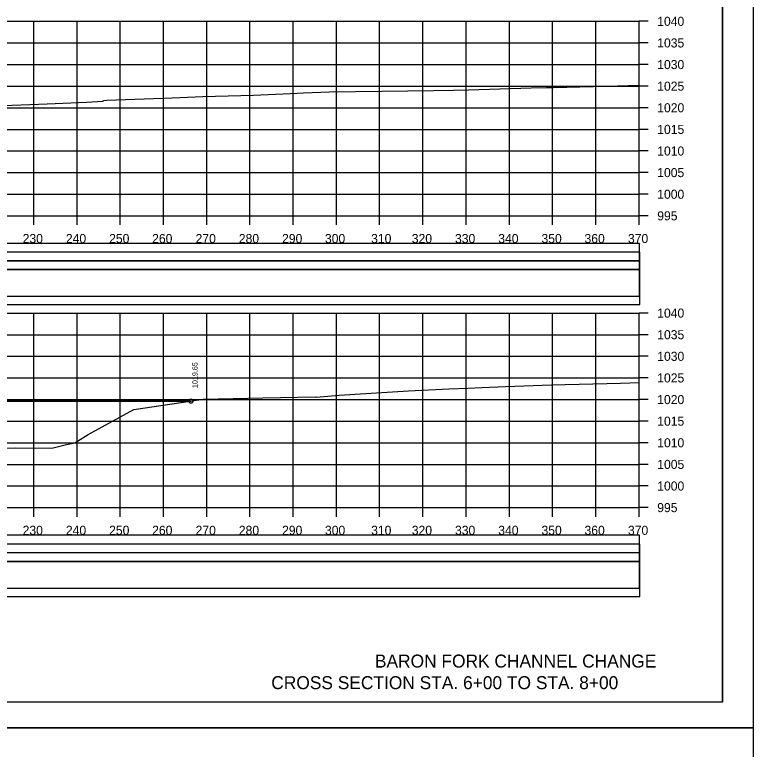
# Model space of a CAD drawing. Extents: x 1370565 to 1374448, y 301010 to 304637.
# Drawn here: x 1374277.1 to 1374447.9, y 301728.1 to 301898 of the extents above; entities that cross this region are included whole.
import ezdxf

# ---------------------------------------------------------------- set-up
doc = ezdxf.new("R2010")
doc.units = 0
for name, color, linetype in [('Default', 7, 'Continuous'), ('R_Axis', 7, 'Continuous'), ('R_Axis Annot', 7, 'Continuous'), ('R_Border', 7, 'Continuous'), ('R_Contours', 7, 'Continuous'), ('R_Draft', 7, 'Continuous'), ('R_Drive', 7, 'Continuous'), ('R_Exist Surface', 7, 'Continuous'), ('R_Fin Surface', 7, 'Continuous'), ('R_Grid', 7, 'Continuous'), ('R_No Plot', 7, 'Continuous'), ('R_Xsect Elev', 7, 'Continuous')]:
    doc.layers.add(name, color=color, linetype=linetype)

msp = doc.modelspace()

# ---------------------------------------------------------------- linework, layer by layer
at = {"layer": 'Default'}
for points in [[(1373981.44, 301841.09), (1374421.61, 301841.09), (1374421.61, 301845.08), (1373981.44, 301845.08)], [(1373981.44, 301832.86), (1374421.61, 301832.86), (1374421.61, 301841.01), (1373981.44, 301841.01)], [(1373981.44, 301773.59), (1374421.61, 301773.59), (1374421.61, 301777.58), (1373981.44, 301777.58)], [(1373981.44, 301765.36), (1374421.61, 301765.36), (1374421.61, 301773.51), (1373981.44, 301773.51)]]:
    msp.add_lwpolyline(points, close=True, dxfattribs=at)
at = {"layer": 'R_Axis'}
for p, q in [((1374421.52, 301851.46), (1374421.52, 301896.46)), ((1374423.62, 301896.46), (1374421.52, 301896.46)), ((1374423.62, 301891.46), (1374421.52, 301891.46)), ((1374423.62, 301886.46), (1374421.52, 301886.46)), ((1374423.62, 301881.46), (1374421.52, 301881.46)), ((1374423.62, 301876.46), (1374421.52, 301876.46)), ((1374423.62, 301871.46), (1374421.52, 301871.46)), ((1374423.62, 301866.46), (1374421.52, 301866.46)), ((1374423.62, 301861.46), (1374421.52, 301861.46)), ((1374423.62, 301856.46), (1374421.52, 301856.46)), ((1373981.52, 301851.46), (1374421.52, 301851.46)), ((1374281.52, 301849.36), (1374281.52, 301851.46)), ((1374291.52, 301849.36), (1374291.52, 301851.46)), ((1374301.52, 301849.36), (1374301.52, 301851.46)), ((1374311.52, 301849.36), (1374311.52, 301851.46)), ((1374321.52, 301849.36), (1374321.52, 301851.46)), ((1374331.52, 301849.36), (1374331.52, 301851.46)), ((1374341.52, 301849.36), (1374341.52, 301851.46)), ((1374351.52, 301849.36), (1374351.52, 301851.46)), ((1374361.52, 301849.36), (1374361.52, 301851.46)), ((1374371.52, 301849.36), (1374371.52, 301851.46)), ((1374381.52, 301849.36), (1374381.52, 301851.46)), ((1374391.52, 301849.36), (1374391.52, 301851.46)), ((1374401.52, 301849.36), (1374401.52, 301851.46)), ((1374411.52, 301849.36), (1374411.52, 301851.46)), ((1374421.52, 301849.36), (1374421.52, 301851.46)), ((1374423.62, 301851.46), (1374421.52, 301851.46)), ((1374421.52, 301783.96), (1374421.52, 301828.96)), ((1374423.62, 301828.96), (1374421.52, 301828.96)), ((1374423.62, 301823.96), (1374421.52, 301823.96)), ((1374423.62, 301818.96), (1374421.52, 301818.96)), ((1374423.62, 301813.96), (1374421.52, 301813.96)), ((1374423.62, 301808.96), (1374421.52, 301808.96)), ((1374423.62, 301803.96), (1374421.52, 301803.96)), ((1374423.62, 301798.96), (1374421.52, 301798.96)), ((1374423.62, 301793.96), (1374421.52, 301793.96)), ((1374423.62, 301788.96), (1374421.52, 301788.96)), ((1373981.52, 301783.96), (1374421.52, 301783.96)), ((1374281.52, 301781.86), (1374281.52, 301783.96)), ((1374291.52, 301781.86), (1374291.52, 301783.96)), ((1374301.52, 301781.86), (1374301.52, 301783.96)), ((1374311.52, 301781.86), (1374311.52, 301783.96)), ((1374321.52, 301781.86), (1374321.52, 301783.96)), ((1374331.52, 301781.86), (1374331.52, 301783.96)), ((1374341.52, 301781.86), (1374341.52, 301783.96)), ((1374351.52, 301781.86), (1374351.52, 301783.96)), ((1374361.52, 301781.86), (1374361.52, 301783.96)), ((1374371.52, 301781.86), (1374371.52, 301783.96)), ((1374381.52, 301781.86), (1374381.52, 301783.96)), ((1374391.52, 301781.86), (1374391.52, 301783.96)), ((1374401.52, 301781.86), (1374401.52, 301783.96)), ((1374411.52, 301781.86), (1374411.52, 301783.96)), ((1374421.52, 301781.86), (1374421.52, 301783.96)), ((1374423.62, 301783.96), (1374421.52, 301783.96))]:
    msp.add_line(p, q, dxfattribs=at)
at = {"layer": 'R_Border'}
for q in [(1374440.79, 302047.15), (1373966.52, 301738.96)]:
    msp.add_line((1374440.79, 301738.96), q, dxfattribs=at)
at = {"layer": 'R_Contours'}
for points in [[(1374317.68, 301808.61), (1374266.85, 301808.56), (1374264.61, 301808.56), (1374254.84, 301808.55), (1374231.88, 301808.53), (1374221.77, 301808.52), (1374217.78, 301808.51), (1374206.15, 301808.5), (1374200.02, 301808.49), (1374182.07, 301808.48), (1374172.35, 301808.47), (1374169.22, 301808.46), (1374168.09, 301808.46), (1374141.64, 301808.44), (1374139.37, 301808.43), (1374126.85, 301808.42), (1374106.89, 301801.84)], [(1374262.96, 301797.71), (1374277.22, 301797.77), (1374285.69, 301797.72), (1374289.11, 301798.56), (1374290.99, 301798.97), (1374294.09, 301800.91), (1374304.66, 301806.64), (1374307.31, 301807.01), (1374317.68, 301808.59)], [(1374317.68, 301808.59), (1374317.68, 301808.61)]]:
    msp.add_lwpolyline(points, dxfattribs=at)
at = {"layer": 'R_Drive'}
for points in [[(1373981.52, 301839.07), (1374421.73, 301839.07), (1374421.73, 301843.06), (1373981.52, 301843.06)], [(1373981.52, 301830.92), (1374421.73, 301830.92), (1374421.73, 301839.07), (1373981.52, 301839.07)], [(1373981.52, 301771.53), (1374421.73, 301771.53), (1374421.73, 301775.53), (1373981.52, 301775.53)], [(1373981.52, 301763.39), (1374421.73, 301763.39), (1374421.73, 301771.53), (1373981.52, 301771.53)]]:
    msp.add_lwpolyline(points, close=True, dxfattribs=at)
at = {"layer": 'R_Exist Surface'}
for points in [[(1374272.42, 301876.91), (1374284.59, 301877.4), (1374293.72, 301877.76), (1374297.48, 301877.95), (1374297.6, 301878.03), (1374297.75, 301878.18), (1374298.42, 301878.2), (1374313.51, 301878.74), (1374320.6, 301879.07), (1374329.43, 301879.29), (1374332.33, 301879.35), (1374335.71, 301879.5), (1374340.89, 301879.76), (1374343.94, 301879.93), (1374349.93, 301880.12), (1374374.08, 301880.48), (1374378.63, 301880.56), (1374382.04, 301880.62), (1374396.53, 301881.04), (1374400.08, 301881.13), (1374401.71, 301881.18), (1374414.01, 301881.47), (1374421.52, 301881.66)], [(1374262.96, 301797.71), (1374277.22, 301797.77), (1374285.69, 301797.72), (1374289.11, 301798.56), (1374290.99, 301798.97), (1374294.09, 301800.91), (1374304.66, 301806.64), (1374307.31, 301807.01), (1374320.72, 301809.05), (1374334.5, 301809.34), (1374346.67, 301809.61), (1374346.9, 301809.53), (1374346.9, 301809.53), (1374346.93, 301809.52), (1374352.15, 301809.97), (1374353.4, 301810.05), (1374368.2, 301810.96), (1374377.55, 301811.45), (1374381.91, 301811.61), (1374385.21, 301811.73), (1374390.64, 301811.95), (1374401.3, 301812.35), (1374417.26, 301812.77), (1374421.52, 301812.91)]]:
    msp.add_lwpolyline(points, dxfattribs=at)
at = {"layer": 'R_Fin Surface'}
msp.add_lwpolyline([(1374266.85, 301808.56), (1374317.68, 301808.61), (1374317.85, 301808.61)], dxfattribs=at)
at = {"layer": 'R_Grid'}
for p, q in [((1373981.52, 301896.46), (1374421.52, 301896.46)), ((1374281.52, 301851.46), (1374281.52, 301896.46)), ((1374291.52, 301851.46), (1374291.52, 301896.46)), ((1374301.52, 301851.46), (1374301.52, 301896.46)), ((1374311.52, 301851.46), (1374311.52, 301896.46)), ((1374321.52, 301851.46), (1374321.52, 301896.46)), ((1374331.52, 301851.46), (1374331.52, 301896.46)), ((1374341.52, 301851.46), (1374341.52, 301896.46)), ((1374351.52, 301851.46), (1374351.52, 301896.46)), ((1374361.52, 301851.46), (1374361.52, 301896.46)), ((1374371.52, 301851.46), (1374371.52, 301896.46)), ((1374381.52, 301851.46), (1374381.52, 301896.46)), ((1374391.52, 301851.46), (1374391.52, 301896.46)), ((1374401.52, 301851.46), (1374401.52, 301896.46)), ((1374411.52, 301851.46), (1374411.52, 301896.46)), ((1374421.52, 301851.46), (1374421.52, 301896.46)), ((1373981.52, 301891.46), (1374421.52, 301891.46)), ((1373981.52, 301886.46), (1374421.52, 301886.46)), ((1373981.52, 301881.46), (1374421.52, 301881.46)), ((1373981.52, 301876.46), (1374421.52, 301876.46)), ((1373981.52, 301871.46), (1374421.52, 301871.46)), ((1373981.52, 301866.46), (1374421.52, 301866.46)), ((1373981.52, 301861.46), (1374421.52, 301861.46)), ((1373981.52, 301856.46), (1374421.52, 301856.46)), ((1373981.52, 301851.46), (1374421.52, 301851.46)), ((1373981.52, 301828.96), (1374421.52, 301828.96)), ((1374281.52, 301783.96), (1374281.52, 301828.96)), ((1374291.52, 301783.96), (1374291.52, 301828.96)), ((1374301.52, 301783.96), (1374301.52, 301828.96)), ((1374311.52, 301783.96), (1374311.52, 301828.96)), ((1374321.52, 301783.96), (1374321.52, 301828.96)), ((1374331.52, 301783.96), (1374331.52, 301828.96)), ((1374341.52, 301783.96), (1374341.52, 301828.96)), ((1374351.52, 301783.96), (1374351.52, 301828.96)), ((1374361.52, 301783.96), (1374361.52, 301828.96)), ((1374371.52, 301783.96), (1374371.52, 301828.96)), ((1374381.52, 301783.96), (1374381.52, 301828.96)), ((1374391.52, 301783.96), (1374391.52, 301828.96)), ((1374401.52, 301783.96), (1374401.52, 301828.96)), ((1374411.52, 301783.96), (1374411.52, 301828.96)), ((1374421.52, 301783.96), (1374421.52, 301828.96)), ((1373981.52, 301823.96), (1374421.52, 301823.96)), ((1373981.52, 301818.96), (1374421.52, 301818.96)), ((1373981.52, 301813.96), (1374421.52, 301813.96)), ((1373981.52, 301808.96), (1374421.52, 301808.96)), ((1373981.52, 301803.96), (1374421.52, 301803.96)), ((1373981.52, 301798.96), (1374421.52, 301798.96)), ((1373981.52, 301793.96), (1374421.52, 301793.96)), ((1373981.52, 301788.96), (1374421.52, 301788.96)), ((1373981.52, 301783.96), (1374421.52, 301783.96))]:
    msp.add_line(p, q, dxfattribs=at)
at = {"layer": 'R_No Plot'}
for p, q in [((1373947.92, 301733), (1374447.92, 301733)), ((1373947.92, 301732.99), (1374447.92, 301732.99))]:
    msp.add_line(p, q, dxfattribs=at)
for points in [[(1373947.91, 302053), (1374447.92, 302053), (1374447.92, 301732.99), (1373947.91, 301732.99)], [(1374317.4, 302047.15), (1374346.83, 302047.15), (1374346.83, 302032.33), (1374371, 302032.33), (1374405.8, 302032.33), (1374405.98, 301990.1), (1374440.79, 301990.1), (1374440.79, 301738.96), (1373966.52, 301738.96), (1373966.52, 302047.15)], [(1373947.91, 301732.99), (1374447.92, 301732.99), (1374447.92, 301412.98), (1373947.91, 301412.98)]]:
    msp.add_lwpolyline(points, close=True, dxfattribs=at)
msp.add_circle((1374317.85, 301808.61), 0.5, dxfattribs=at)

# ---------------------------------------------------------------- texts
at = {"layer": 'R_Axis Annot'}
for s, p in [('1040', (1374425.72, 301895.41)), ('1035', (1374425.72, 301890.41)), ('1030', (1374425.72, 301885.41)), ('1025', (1374425.72, 301880.41)), ('1020', (1374425.72, 301875.41)), ('1015', (1374425.72, 301870.41)), ('1010', (1374425.72, 301865.41)), ('1005', (1374425.72, 301860.41)), ('1000', (1374425.72, 301855.41)), ('995', (1374425.72, 301850.41)), ('230', (1374278.95, 301845.16)), ('240', (1374288.95, 301845.16)), ('250', (1374298.95, 301845.16)), ('260', (1374308.9, 301845.16)), ('270', (1374318.95, 301845.16)), ('280', (1374328.95, 301845.16)), ('290', (1374338.95, 301845.16)), ('300', (1374348.87, 301845.16)), ('310', (1374359.55, 301845.16)), ('320', (1374368.95, 301845.16)), ('330', (1374378.95, 301845.16)), ('340', (1374388.95, 301845.16)), ('350', (1374398.95, 301845.16)), ('360', (1374408.9, 301845.16)), ('370', (1374418.95, 301845.16)), ('1040', (1374425.72, 301827.91)), ('1035', (1374425.72, 301822.91)), ('1030', (1374425.72, 301817.91)), ('1025', (1374425.72, 301812.91)), ('1020', (1374425.72, 301807.91)), ('1015', (1374425.72, 301802.91)), ('1010', (1374425.72, 301797.91)), ('1005', (1374425.72, 301792.91)), ('1000', (1374425.72, 301787.91)), ('995', (1374425.72, 301782.91)), ('230', (1374278.95, 301777.66)), ('240', (1374288.95, 301777.66)), ('250', (1374298.95, 301777.66)), ('260', (1374308.9, 301777.66)), ('270', (1374318.95, 301777.66)), ('280', (1374328.95, 301777.66)), ('290', (1374338.95, 301777.66)), ('300', (1374348.87, 301777.66)), ('310', (1374359.55, 301777.66)), ('320', (1374368.95, 301777.66)), ('330', (1374378.95, 301777.66)), ('340', (1374388.95, 301777.66)), ('350', (1374398.95, 301777.66)), ('360', (1374408.9, 301777.66)), ('370', (1374418.95, 301777.66))]:
    msp.add_text(s, height=2.1, dxfattribs=at).set_placement(p)
at = {"layer": 'R_Draft'}
for s, p in [(' BARON FORK CHANNEL CHANGE', (1374359.31, 301746.96)), ('CROSS SECTION STA. 6+00 TO STA. 8+00', (1374336.45, 301741.96))]:
    msp.add_text(s, height=3, dxfattribs=at).set_placement(p)
at = {"layer": 'R_Xsect Elev'}
msp.add_text('1019.65', height=1.2, rotation=90, dxfattribs=at).set_placement((1374319.4, 301811.61))

doc.saveas('drawing.dxf')
